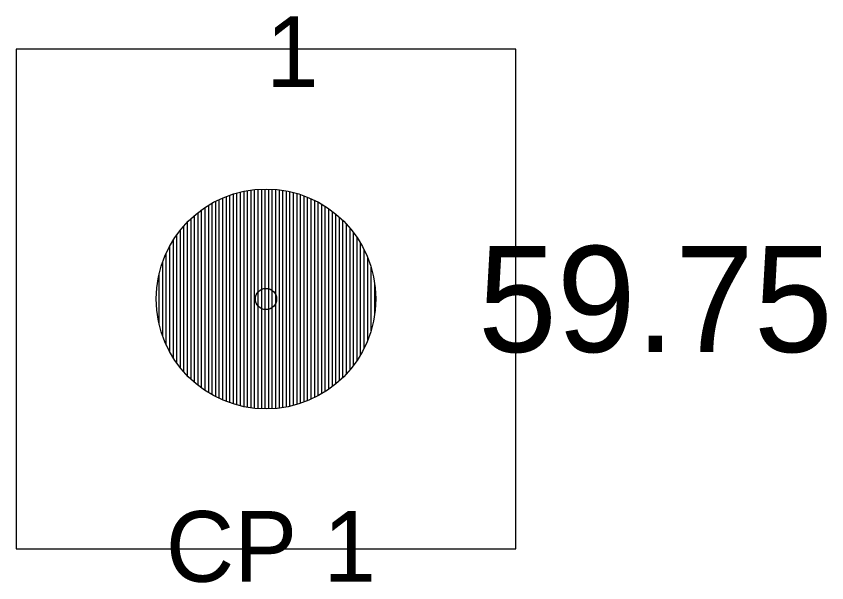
# Model space of a CAD drawing. Extents: x 2396531 to 2397633, y 770203 to 772837.
# Drawn here: x 2396600.93 to 2396612.4, y 772828.53 to 772836.54 of the extents above; entities that cross this region are included whole.
import ezdxf

# ---------------------------------------------------------------- set-up
doc = ezdxf.new("R2010")
doc.units = 0
for name, color, linetype in [('RD_HC_Survey', 7, 'Continuous'), ('RD_HC_Survey_ELEV', 7, 'Continuous'), ('RD_HC_Survey_txCode', 7, 'Continuous'), ('RD_SMD_Locator', 7, 'Continuous')]:
    doc.layers.add(name, color=color, linetype=linetype)

msp = doc.modelspace()

# ---------------------------------------------------------------- linework, layer by layer
at = {"layer": 'RD_HC_Survey'}
for p, q in [((2396604.253, 772831.005), (2396604.253, 772834.085)), ((2396604.303, 772830.999), (2396604.303, 772834.091)), ((2396604.353, 772830.994), (2396604.353, 772834.095)), ((2396604.403, 772830.991), (2396604.403, 772834.098)), ((2396604.453, 772830.99), (2396604.453, 772834.099)), ((2396604.503, 772830.991), (2396604.503, 772834.099)), ((2396604.553, 772830.993), (2396604.553, 772834.097)), ((2396604.603, 772830.996), (2396604.603, 772834.093)), ((2396604.653, 772831.002), (2396604.653, 772834.088)), ((2396603.853, 772831.116), (2396603.853, 772833.974)), ((2396603.903, 772831.095), (2396603.903, 772833.994)), ((2396603.953, 772831.077), (2396603.953, 772834.013)), ((2396604.003, 772831.06), (2396604.003, 772834.029)), ((2396604.053, 772831.046), (2396604.053, 772834.044)), ((2396604.103, 772831.033), (2396604.103, 772834.057)), ((2396604.153, 772831.022), (2396604.153, 772834.068)), ((2396604.203, 772831.012), (2396604.203, 772834.077)), ((2396604.703, 772831.009), (2396604.703, 772834.081)), ((2396604.753, 772831.017), (2396604.753, 772834.072)), ((2396604.803, 772831.027), (2396604.803, 772834.062)), ((2396604.853, 772831.039), (2396604.853, 772834.05)), ((2396604.903, 772831.053), (2396604.903, 772834.036)), ((2396604.953, 772831.069), (2396604.953, 772834.021)), ((2396605.003, 772831.086), (2396605.003, 772834.003)), ((2396605.053, 772831.106), (2396605.053, 772833.984)), ((2396603.653, 772831.219), (2396603.653, 772833.871)), ((2396603.703, 772831.19), (2396603.703, 772833.9)), ((2396603.753, 772831.163), (2396603.753, 772833.927)), ((2396603.803, 772831.138), (2396603.803, 772833.951)), ((2396605.103, 772831.127), (2396605.103, 772833.962)), ((2396605.153, 772831.151), (2396605.153, 772833.939)), ((2396605.203, 772831.177), (2396605.203, 772833.913)), ((2396605.253, 772831.205), (2396605.253, 772833.885)), ((2396603.503, 772831.324), (2396603.503, 772833.766)), ((2396603.553, 772831.286), (2396603.553, 772833.804)), ((2396603.603, 772831.251), (2396603.603, 772833.839)), ((2396605.303, 772831.235), (2396605.303, 772833.854)), ((2396605.353, 772831.269), (2396605.353, 772833.821)), ((2396605.403, 772831.305), (2396605.403, 772833.784)), ((2396605.453, 772831.345), (2396605.453, 772833.745)), ((2396603.353, 772831.458), (2396603.353, 772833.631)), ((2396603.403, 772831.409), (2396603.403, 772833.68)), ((2396603.453, 772831.365), (2396603.453, 772833.725)), ((2396605.503, 772831.388), (2396605.503, 772833.702)), ((2396605.553, 772831.434), (2396605.553, 772833.655)), ((2396603.253, 772831.571), (2396603.253, 772833.518)), ((2396603.303, 772831.512), (2396603.303, 772833.578)), ((2396605.603, 772831.486), (2396605.603, 772833.604)), ((2396605.653, 772831.542), (2396605.653, 772833.547)), ((2396603.203, 772831.637), (2396603.203, 772833.453)), ((2396605.703, 772831.605), (2396605.703, 772833.485)), ((2396605.753, 772831.674), (2396605.753, 772833.415)), ((2396603.103, 772831.795), (2396603.103, 772833.294)), ((2396603.153, 772831.711), (2396603.153, 772833.379)), ((2396605.803, 772831.753), (2396605.803, 772833.336)), ((2396603.053, 772831.894), (2396603.053, 772833.195)), ((2396605.853, 772831.845), (2396605.853, 772833.245)), ((2396603.003, 772832.016), (2396603.003, 772833.074)), ((2396605.903, 772831.954), (2396605.903, 772833.135)), ((2396605.953, 772832.095), (2396605.953, 772832.995)), ((2396602.953, 772832.183), (2396602.953, 772832.907)), ((2396606.003, 772832.319), (2396606.003, 772832.771))]:
    msp.add_line(p, q, dxfattribs=at)
msp.add_lwpolyline([(2396608, 772836.08), (2396600.929, 772836.08), (2396600.929, 772829.009), (2396608, 772829.009)], close=True, dxfattribs=at)
msp.add_circle((2396604.464, 772832.545), 1.555, dxfattribs=at)
at = {"layer": 'RD_SMD_Locator'}
msp.add_circle((2396604.464, 772832.545), 0.15, dxfattribs=at)

# ---------------------------------------------------------------- texts
at = {"layer": 'RD_HC_Survey_ELEV'}
msp.add_text('59.75', height=1.5, dxfattribs=at).set_placement((2396607.464, 772831.795))
at = {"layer": 'RD_HC_Survey_txCode'}
for s, p in [('1', (2396604.464, 772835.545)), ('CP 1', (2396603.047, 772828.545))]:
    msp.add_text(s, height=1, dxfattribs=at).set_placement(p)

doc.saveas('drawing.dxf')
